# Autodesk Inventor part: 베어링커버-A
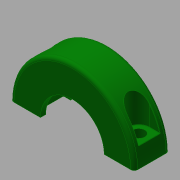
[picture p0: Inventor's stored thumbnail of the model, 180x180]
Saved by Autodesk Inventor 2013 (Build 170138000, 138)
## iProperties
Created: 2018-01
Part Number: 베어링커버-A
Material: 일반
Document SubType Name: Modeling
Designer: mduedu
Density: 1 g/cm^3
Author: mduedu
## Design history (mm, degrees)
sketch "스케치1"
  geometry: L1 (-17.5, 0)-(17.5, 0); A1 r 17.5 centre (0, 0) between (-17.5, 0) and (17.5, 0); 2 further points
  constraints: 2 coincident, 2 end point, 2 point on circle, 1 centre point, 1 horizontal, 1 midpoint
  dimensions: "d0" = 35 diameter of A1
extrude "돌출1" new body sketch "스케치1" stored distance "d1" = 10; taper "d2" = 0 deg
sketch "스케치2"
  geometry: C1 r 11 at (0, 0); C2 r 9 at (0, 0); 1 further point
  constraints: 2 centre point, 2 coincident
  dimensions: "d3" = 22 diameter of C1; "d4" = 18 diameter of C2
extrude "돌출2" cut sketch "스케치2" stored distance "d5" = 7; taper "d6" = 0 deg
extrude "돌출3" cut sketch "스케치2" stored distance "d7" = 7; taper "d8" = 0 deg
fillet "모깎기1" dims "d9" = 0.3
fillet "모깎기2" dims "d10" = 1
node "작업 평면1"
sketch "스케치3"
  geometry: L1 (-15.5, -3.5)-(33.5, -3.5) reference; L2 (-4.771, -6.5)-(-7.771, -6.5); L3 (-7.771, -6.5)-(-7.771, -0.5); L4 (-7.771, -0.5)-(-4.771, -0.5); L5 (-0.46, -7)-(1.517, -7) reference; L6 (1.517, -7)-(1.517, -8.5) reference; L7 (1.517, -8.5)-(-6.724, -8.5) reference; L8 (-7.771, -7.5)-(-7.771, 0.5) reference; L9 (-6.724, 1.5)-(1.517, 1.5) reference; L10 (1.517, 1.5)-(1.517, 0) reference; L11 (1.517, 0)-(-0.46, 0) reference; L12 (-0.798, -0.3)-(-0.798, -6.7) reference; L13 (18.798, -6.7)-(18.798, -0.3) reference; L14 (18.46, 0)-(16.483, 0) reference; L15 (16.483, 0)-(16.483, 1.5) reference; L16 (16.483, 1.5)-(24.724, 1.5) reference; L17 (25.771, 0.5)-(25.771, -7.5) reference; L18 (24.724, -8.5)-(16.483, -8.5) reference; L19 (16.483, -8.5)-(16.483, -7) reference; L20 (16.483, -7)-(18.46, -7) reference; A1 r 3 centre (-4.771, -3.5) between (-4.771, -6.5) and (-4.771, -0.5); 1 further point
  constraints: 6 end point, 2 point on circle, 2 tangent, 1 centre point, 1 collinear, 1 horizontal, 1 parallel, 1 perpendicular, 1 point on line, 8 other
  dimensions: "d12" = 6 distance between parallel lines of L4 L2; "d14" = 6 dimension on A1 L3
extrude "돌출4" cut sketch "스케치3" stored distance "d15" = 0; taper "d16" = 0 deg
sketch "스케치4"
  geometry: 7 further points
  constraints: 4 vertical alignment, 2 horizontal alignment
sketch "스케치5"
  geometry: 2 further points
  constraints: 2 other
hole "구멍1" sketch "스케치5" at (-22.771, 3.5), (4.771, 3.5) diameter "d17" = 3.4; stored, may be unused: countersink angle "d21" = 90 deg, drill point angle "d23" = 0 deg; dims "d18" = 6, "d19" = 4, "d20" = 2, "d22" = 8
fillet "모깎기3" dims "d24" = 0.1
node "솔리드1"
mirror "대칭1"
node "절단 모서리 투영1"
other parameters: "d11" = -5
